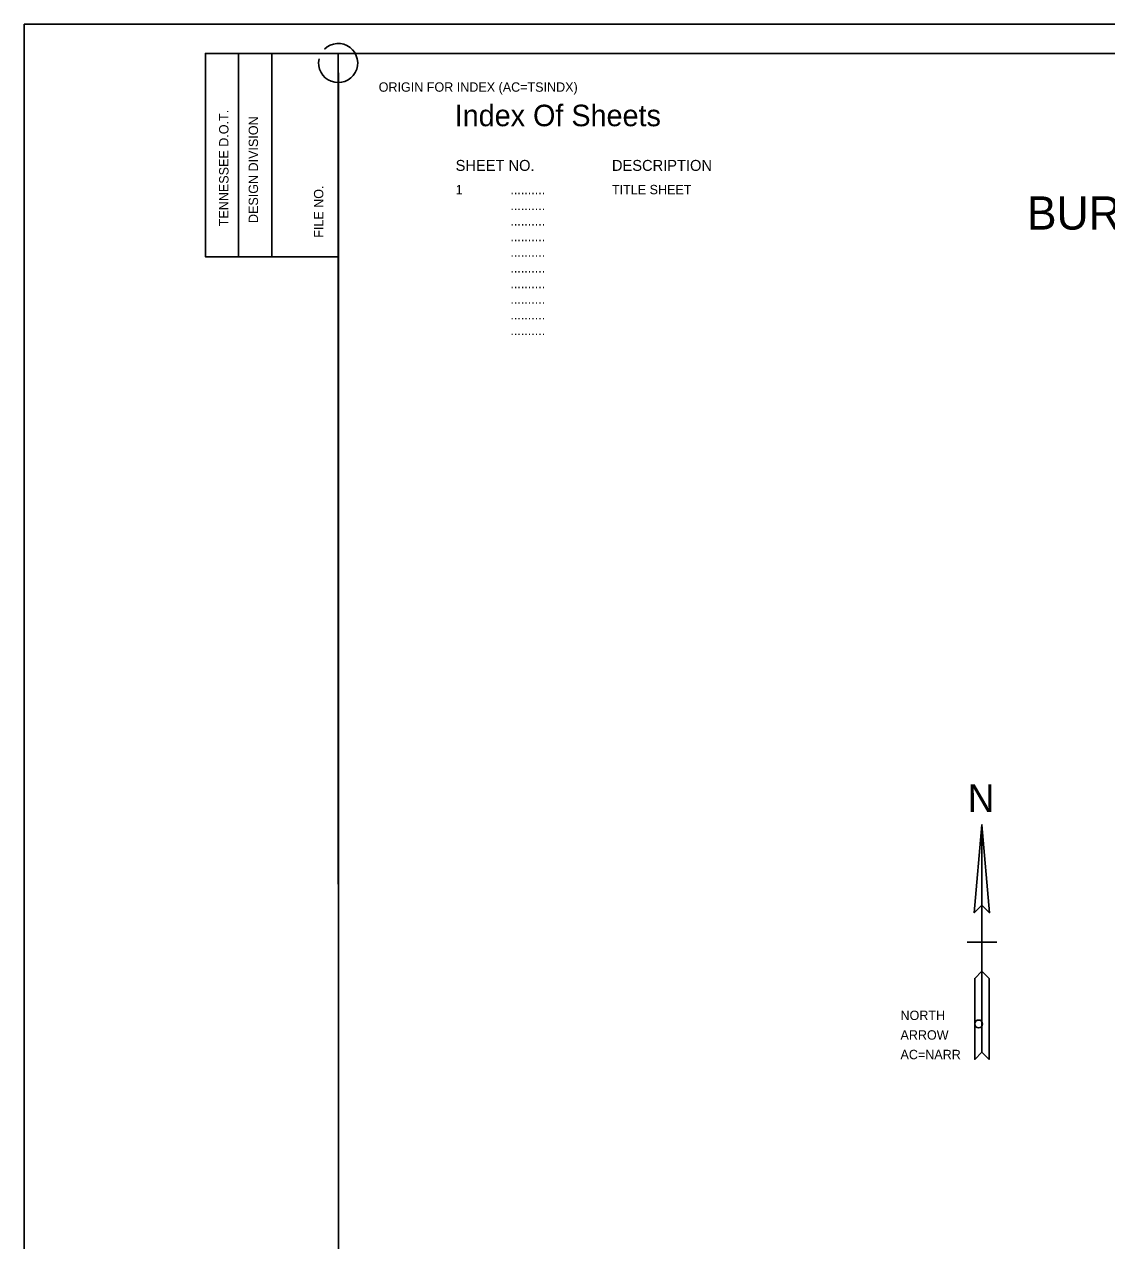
# Model space of a CAD drawing. Extents: x 1623795.1 to 1623879, y 427353.8 to 427391.8.
# Drawn here: x 1623795.06 to 1623808.9, y 427374.3 to 427389.86 of the extents above; entities that cross this region are included whole.
import ezdxf

# ---------------------------------------------------------------- set-up
doc = ezdxf.new("R2010")
doc.units = 0
for name, color, linetype in [('DESIGN - CENTERLINE - Proposed Text', 7, 'Continuous'), ('DESIGN - PUBLIC HEARING - Shapes', 7, 'Continuous'), ('DESIGN - SCRATCH - User 1', 7, 'Continuous'), ('DESIGN - SHEET - Light Grid', 7, 'Continuous'), ('DESIGN - SHEET - Linework', 7, 'Continuous')]:
    doc.layers.add(name, color=color, linetype=linetype)

msp = doc.modelspace()

# ---------------------------------------------------------------- linework, layer by layer
at = {"layer": 'DESIGN - CENTERLINE - Proposed Text'}
for p, q in [((1623807.309, 427378.123), (1623807.12, 427378.123)), ((1623807.499, 427378.123), (1623807.309, 427378.123))]:
    msp.add_line(p, q, dxfattribs=at)
msp.add_lwpolyline([(1623807.309, 427379.623), (1623807.211, 427378.497), (1623807.309, 427378.595), (1623807.408, 427378.497), (1623807.309, 427379.623), (1623807.309, 427376.714), (1623807.4, 427376.623), (1623807.4, 427377.659), (1623807.309, 427377.75), (1623807.218, 427377.659), (1623807.218, 427376.623), (1623807.309, 427376.714)], dxfattribs=at)
for points in [[(1623807.309, 427378.595), (1623807.408, 427378.497), (1623807.309, 427379.623)], [(1623807.218, 427376.623), (1623807.309, 427376.714), (1623807.309, 427377.75), (1623807.218, 427377.659)]]:
    msp.add_lwpolyline(points, close=True, dxfattribs=at)
at = {"layer": 'DESIGN - PUBLIC HEARING - Shapes'}
msp.add_lwpolyline([(1623799.078, 427389.485), (1623830.562, 427389.485), (1623830.562, 427368.235), (1623799.079, 427368.235)], close=True, dxfattribs=at)
at = {"layer": 'DESIGN - SCRATCH - User 1'}
msp.add_circle((1623807.268, 427377.076), 0.05, dxfattribs=at)
msp.add_arc((1623799.077, 427389.363), 0.25, 167.5258, 134.6021, dxfattribs=at)
at = {"layer": 'DESIGN - SHEET - Linework'}
for p, q in [((1623795.063, 427389.858), (1623831.063, 427389.858)), ((1623795.063, 427367.858), (1623795.063, 427389.858)), ((1623797.803, 427389.485), (1623797.803, 427386.887)), ((1623798.229, 427389.485), (1623798.229, 427386.887))]:
    msp.add_line(p, q, dxfattribs=at)
for points in [[(1623799.079, 427389.485), (1623797.378, 427389.485), (1623797.378, 427386.887), (1623799.079, 427386.887)], [(1623799.078, 427389.485), (1623830.562, 427389.485), (1623830.562, 427368.235), (1623799.079, 427368.235), (1623799.079, 427389.236)]]:
    msp.add_lwpolyline(points, dxfattribs=at)

# ---------------------------------------------------------------- texts
at = {"layer": 'DESIGN - CENTERLINE - Proposed Text'}
msp.add_text('N', height=0.354, dxfattribs=at).set_placement((1623807.128, 427379.785))
at = {"layer": 'DESIGN - SCRATCH - User 1'}
for s, height, p in [('ORIGIN FOR INDEX (AC=TSINDX)', 0.11999, (1623799.595, 427388.996)), ('NORTH', 0.12, (1623806.268, 427377.126)), ('ARROW', 0.12, (1623806.268, 427376.875)), ('AC=NARR', 0.12, (1623806.268, 427376.625))]:
    msp.add_text(s, height=height, dxfattribs=at).set_placement(p)
at = {"layer": 'DESIGN - SHEET - Light Grid'}
for s, height, p in [('Index Of Sheets', 0.27499, (1623800.567, 427388.555)), ('BUREAU OF PLANNING AND DEVELOPMENT', 0.425, (1623807.885, 427387.233))]:
    msp.add_text(s, height=height, dxfattribs=at).set_placement(p)
at = {"layer": 'DESIGN - SHEET - Linework'}
for s, height, p in [('TENNESSEE D.O.T.', 0.11999, (1623797.674, 427387.276)), ('DESIGN DIVISION', 0.11999, (1623798.052, 427387.317)), ('FILE NO.', 0.12, (1623798.887, 427387.128))]:
    msp.add_text(s, height=height, rotation=90, dxfattribs=at).set_placement(p)
for s, height, p in [('SHEET NO.', 0.14, (1623800.579, 427387.984)), ('DESCRIPTION', 0.14, (1623802.578, 427387.984)), ('1', 0.12, (1623800.579, 427387.685)), ('..........', 0.12, (1623801.279, 427387.685)), ('TITLE SHEET', 0.11999, (1623802.578, 427387.685)), ('..........', 0.12, (1623801.279, 427387.484)), ('..........', 0.12, (1623801.279, 427387.284)), ('..........', 0.12, (1623801.279, 427387.085)), ('..........', 0.12, (1623801.279, 427386.885)), ('..........', 0.12, (1623801.279, 427386.684)), ('..........', 0.12, (1623801.279, 427386.484)), ('..........', 0.12, (1623801.279, 427386.285)), ('..........', 0.12, (1623801.279, 427386.085)), ('..........', 0.12, (1623801.279, 427385.885))]:
    msp.add_text(s, height=height, dxfattribs=at).set_placement(p)

doc.saveas('drawing.dxf')
